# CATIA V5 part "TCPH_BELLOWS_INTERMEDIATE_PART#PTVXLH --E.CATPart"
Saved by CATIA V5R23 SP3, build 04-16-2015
Part number: TCPH_BELLOWS_INTERMEDIATE_PART#PTVXKY
Revision: --E
Nomenclature: _
Description: TCPH_BELLOWS_INTERMEDIATE_PART
Property "AT": "PD"
Property "REP": "CM"
Property "External Part ID": "_"
Property "Description Modification": "FDR Model"
Property "PREF": "Y"
Property "LONG": "_"
Property "PBS 1": "24"
Property "PBS 2": "CR"
Property "PBS 3": "LC"
Property "DEPT": "_"
Property "DIVN": "_"
Property "GROUP": "_"
Property "UNIT": "_"
Property "PARTY": "_"
Property "RO": "IOKIK"
Property "RE": "VITUPIG"
Property "PRO": "---"
Property "Change Type": "Major"
Property "Maturity Level": "CD"
Property "Export Number": "_"
Property "Description Documents": "_"
Property "BOM": "_"
Property "ID": "PTVXKY"
Property "User In Enovia": "VAUQUEJ"
Property "Object Type": "_"
Property "CADENAS_ID": "_"
Property "Life Cycle Status": "Approved"
Material "X2CrNi18-09 1.4307 (304L)": density 8000 kg/m3, Young's modulus 1.93e+11 Pa, Poisson ratio 0.3, thermal expansion 1.6e-05 1/K
Bounding box of the stored display mesh (mm): x 12950 to 13090, y -685 to 685, z -5063.917 to -3722.083
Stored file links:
  C:\Users\pandeym\Desktop\__TCPH\TCPH_BELLOWS_INTERMEDIATE_PART#PTVXLH --E.CATPart
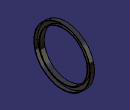
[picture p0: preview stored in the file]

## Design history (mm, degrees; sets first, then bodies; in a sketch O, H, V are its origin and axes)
Set1
  Line1 "CRYOPUMP_CENTER_AXIS": linked copy from another document
  Sketch1 "BELLOWS_INTERMEDIATE_FLANGE", origin (0, 0, 0), H (-1, 0, 0), V (0, 0, 1), geometry linked from another document
  DatumCurve1 "TCPH_MONITORING_PIPE_LEFT": linked copy from another document
  DatumCurve2 "MONITORING_PIPE_PROFIL": linked copy from another document
  Sketch2 "MONITORING_PIPE_SECTION", origin (0, 685, 0), H (-1, 0, 0), V (0, 0, 1), geometry linked from another document
Set2
  Extract1: ExtractElem edge of Sketch2
  Extract2: ExtractElem edge of Symmetry1
  Symmetry1: ToTransfor Sketch2, Reference zx-plane
  Extract3: ExtractElem edge of Symmetry1
Body1 (main body)
  Shaft1: profile Sketch1, axis Line1, angle 360
  Pad1: profile Sketch2, direction (0, -1, 0), length 25
  Pocket1: profile Extract1, through (limit type 6)
  Pad2: profile Symmetry1, up to the existing solid (limit type 2)
  Pocket2: profile Extract2, through (limit type 6)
